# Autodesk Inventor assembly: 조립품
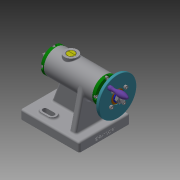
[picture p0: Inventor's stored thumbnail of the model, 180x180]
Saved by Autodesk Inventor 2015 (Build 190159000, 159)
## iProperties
Created: 2022-06
Part Number: 조립품
Document SubType Name: Assembly
Designer: 104-1
Author: 104-1
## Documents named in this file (18)
- C:\Users\104-1\Desktop\720606V1014\조립품.iam
- C:\Users\104-1\Desktop\720606V1014\Ű 4 x 4 x 10.ipt
- C:\Users\104-1\Desktop\720606V1014\나사.ipt
- C:\Users\104-1\Desktop\720606V1014\나사축.ipt
- C:\Users\104-1\Desktop\720606V1014\너트 M8.ipt
- C:\Users\104-1\Desktop\720606V1014\돌림판.ipt
- C:\Users\104-1\Desktop\720606V1014\멈춤나사 M3.ipt
- C:\Users\104-1\Desktop\720606V1014\본체.ipt
- C:\Users\104-1\Desktop\720606V1014\볼트 M3.ipt
- C:\Users\104-1\Desktop\720606V1014\부시.ipt
- C:\Users\104-1\Desktop\720606V1014\센터.ipt
- C:\Users\104-1\Desktop\720606V1014\센터홀더.ipt
- C:\Users\104-1\Desktop\720606V1014\슬리브.ipt
- C:\Users\104-1\Desktop\720606V1014\와셔.ipt
- C:\Users\104-1\Desktop\720606V1014\중공축.ipt
- C:\Users\104-1\Desktop\720606V1014\커버.ipt
- C:\Users\104-1\Desktop\720606V1014\플랜지.ipt
- C:\Users\104-1\Desktop\720606V1014\핸들.ipt
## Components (3 placed, 3 different names)
1. Ű 4 x 4 x 10:1 — 각도:1, 각도:2
2. 플랜지:1 — 각도:2
3. 핸들:1
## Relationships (2: Angle 2)
- 각도:1 [Angle]: Ű 4 x 4 x 10:1
- 각도:2 [Angle]: Ű 4 x 4 x 10:1 ↔ 플랜지:1
